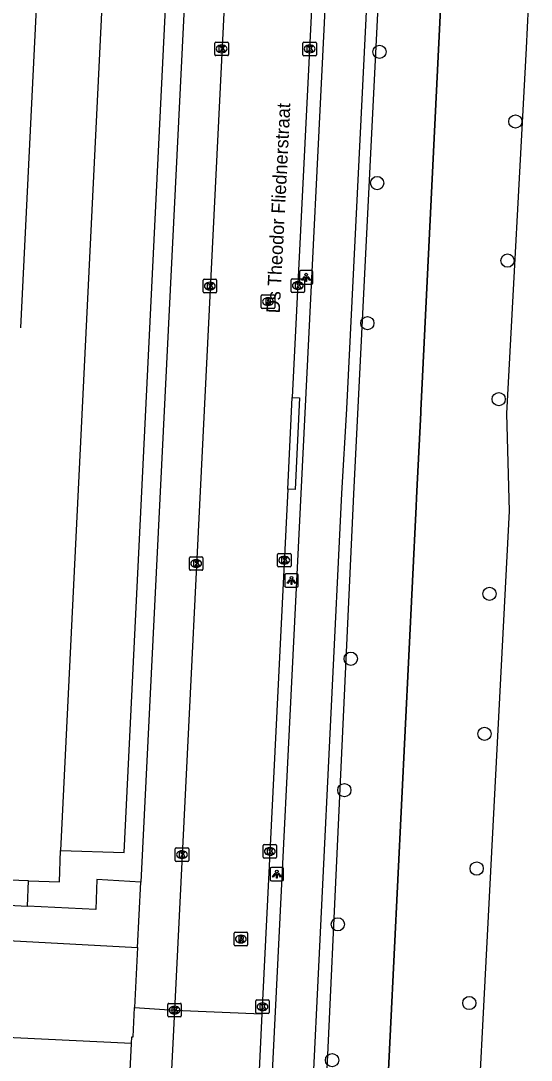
# Model space of a CAD drawing. Extents: x 161761 to 162722, y 384793 to 385405.
# Drawn here: x 162102.1 to 162139.8, y 385048.1 to 385124.9 of the extents above; entities that cross this region are included whole.
import ezdxf

# ---------------------------------------------------------------- set-up
doc = ezdxf.new("R2010")
doc.units = 0
for name, color, linetype in [('IMGEO_Boom', 7, 'Continuous'), ('IMGEO_Fietspad_gesloten', 7, 'Continuous'), ('IMGEO_Groenvoorziening', 7, 'Continuous'), ('IMGEO_Hek', 7, 'Continuous'), ('IMGEO_Kolk', 7, 'Continuous'), ('IMGEO_Lichtpunt', 7, 'Continuous'), ('IMGEO_Openbare_ruimte_label', 7, 'Continuous'), ('IMGEO_Parkeervlak_open', 7, 'Continuous'), ('IMGEO_Rijbaan_lokaal_gesloten', 7, 'Continuous'), ('IMGEO_Rijbaan_lokaal_open', 7, 'Continuous'), ('IMGEO_Rioolput', 7, 'Continuous'), ('IMGEO_Voetpad_open', 7, 'Continuous')]:
    doc.layers.add(name, color=color, linetype=linetype)

msp = doc.modelspace()

# ---------------------------------------------------------------- linework, layer by layer
at = {"layer": 'IMGEO_Boom'}
for centre in [(162128.599, 385122.593), (162138.645, 385117.45), (162128.431, 385112.904), (162138.061, 385107.18), (162127.706, 385102.563), (162137.413, 385096.949), (162136.737, 385082.579), (162126.479, 385077.787), (162136.368, 385072.245), (162126.005, 385068.086), (162135.785, 385062.293), (162125.52, 385058.179), (162135.239, 385052.366), (162125.097, 385048.151)]:
    msp.add_circle(centre, 0.489, dxfattribs=at)
at = {"layer": 'IMGEO_Fietspad_gesloten'}
for points in [[(162134.018, 385254.741), (162126.161, 385096.242), (162125.803, 385089.99), (162122.735, 385027.19)], [(162120.563, 385044.774), (162129.342, 385221.587)]]:
    msp.add_lwpolyline(points, dxfattribs=at)
at = {"layer": 'IMGEO_Groenvoorziening'}
for points in [[(162134.904, 385254.707), (162126.688, 385089.939), (162123.507, 385021.46)], [(162127.975, 385021.202), (162128.056, 385022.862), (162131.31, 385089.036), (162131.34, 385089.671), (162131.648, 385095.933), (162131.658, 385096.124), (162133.367, 385130.823)], [(162139.817, 385130.505), (162139.433, 385122.857), (162137.997, 385095.888), (162138.195, 385088.671), (162134.073, 385009.395)]]:
    msp.add_lwpolyline(points, dxfattribs=at)
at = {"layer": 'IMGEO_Hek'}
for points in [[(162133.367, 385130.823), (162131.658, 385096.124)], [(162131.648, 385095.933), (162131.34, 385089.671)], [(162131.658, 385096.124), (162131.648, 385095.933)], [(162131.31, 385089.036), (162128.056, 385022.862)], [(162131.34, 385089.671), (162131.31, 385089.036)]]:
    msp.add_lwpolyline(points, dxfattribs=at)
at = {"layer": 'IMGEO_Kolk'}
for p, q in [((162116.433, 385122.384), (162116.433, 385123.236)), ((162116.508, 385123.31), (162117.36, 385123.31)), ((162116.921, 385123.09), (162116.946, 385123.09)), ((162117.434, 385123.236), (162117.434, 385122.384)), ((162122.938, 385122.383), (162122.938, 385123.235)), ((162123.013, 385123.309), (162123.865, 385123.309)), ((162123.426, 385123.089), (162123.451, 385123.089)), ((162123.939, 385123.235), (162123.939, 385122.383)), ((162117.36, 385122.31), (162116.508, 385122.31)), ((162116.944, 385122.53), (162116.919, 385122.53)), ((162123.865, 385122.309), (162123.013, 385122.309)), ((162123.449, 385122.529), (162123.424, 385122.529)), ((162122.142, 385105.83), (162122.994, 385105.83)), ((162115.566, 385104.871), (162115.566, 385105.723)), ((162115.641, 385105.797), (162116.493, 385105.797)), ((162116.054, 385105.577), (162116.079, 385105.577)), ((162116.567, 385105.723), (162116.567, 385104.871)), ((162122.067, 385104.904), (162122.067, 385105.756)), ((162122.555, 385105.61), (162122.58, 385105.61)), ((162123.068, 385105.756), (162123.068, 385104.904)), ((162116.493, 385104.797), (162115.641, 385104.797)), ((162116.077, 385105.017), (162116.052, 385105.017)), ((162122.994, 385104.83), (162122.142, 385104.83)), ((162122.578, 385105.05), (162122.553, 385105.05)), ((162114.554, 385084.388), (162114.554, 385085.24)), ((162114.629, 385085.314), (162115.481, 385085.314)), ((162115.555, 385085.24), (162115.555, 385084.388)), ((162121.063, 385084.636), (162121.063, 385085.488)), ((162121.138, 385085.562), (162121.99, 385085.562)), ((162121.551, 385085.342), (162121.576, 385085.342)), ((162122.064, 385085.488), (162122.064, 385084.636)), ((162115.065, 385084.534), (162115.04, 385084.534)), ((162115.042, 385085.094), (162115.067, 385085.094)), ((162121.99, 385084.562), (162121.138, 385084.562)), ((162121.574, 385084.782), (162121.549, 385084.782)), ((162115.481, 385084.314), (162114.629, 385084.314)), ((162113.503, 385062.895), (162113.503, 385063.747)), ((162113.578, 385063.821), (162114.43, 385063.821)), ((162114.504, 385063.747), (162114.504, 385062.895)), ((162119.999, 385063.139), (162119.999, 385063.991)), ((162120.074, 385064.065), (162120.926, 385064.065)), ((162120.487, 385063.845), (162120.512, 385063.845)), ((162121, 385063.991), (162121, 385063.139)), ((162114.014, 385063.041), (162113.989, 385063.041)), ((162113.991, 385063.601), (162114.016, 385063.601)), ((162120.926, 385063.065), (162120.074, 385063.065)), ((162120.51, 385063.285), (162120.485, 385063.285)), ((162114.43, 385062.821), (162113.578, 385062.821)), ((162112.954, 385051.417), (162112.954, 385052.269)), ((162113.029, 385052.343), (162113.881, 385052.343)), ((162113.442, 385052.123), (162113.467, 385052.123)), ((162113.955, 385052.269), (162113.955, 385051.417)), ((162119.453, 385051.668), (162119.453, 385052.52)), ((162119.528, 385052.594), (162120.38, 385052.594)), ((162119.941, 385052.374), (162119.966, 385052.374)), ((162120.454, 385052.52), (162120.454, 385051.668)), ((162113.881, 385051.343), (162113.029, 385051.343)), ((162113.465, 385051.563), (162113.44, 385051.563)), ((162120.38, 385051.594), (162119.528, 385051.594)), ((162119.964, 385051.814), (162119.939, 385051.814))]:
    msp.add_line(p, q, dxfattribs=at)
for points in [[(162116.433, 385122.384), (162116.433, 385123.236)], [(162116.508, 385123.31), (162117.36, 385123.31)], [(162116.754, 385123.01), (162116.877, 385123.01), (162116.877, 385122.859), (162117.007, 385123.01), (162117.171, 385123.01), (162117.025, 385122.859), (162117.178, 385122.61), (162117.026, 385122.61), (162116.941, 385122.774), (162116.877, 385122.707), (162116.877, 385122.61), (162116.754, 385122.61), (162116.754, 385123.01)], [(162117.434, 385123.236), (162117.434, 385122.384)], [(162122.938, 385122.383), (162122.938, 385123.235)], [(162123.013, 385123.309), (162123.865, 385123.309)], [(162123.259, 385123.009), (162123.382, 385123.009), (162123.382, 385122.858), (162123.512, 385123.009), (162123.676, 385123.009), (162123.53, 385122.858), (162123.683, 385122.609), (162123.531, 385122.609), (162123.446, 385122.773), (162123.382, 385122.706), (162123.382, 385122.609), (162123.259, 385122.609), (162123.259, 385123.009)], [(162123.939, 385123.235), (162123.939, 385122.383)], [(162117.36, 385122.31), (162116.508, 385122.31)], [(162123.865, 385122.309), (162123.013, 385122.309)], [(162122.142, 385105.83), (162122.994, 385105.83)], [(162115.566, 385104.871), (162115.566, 385105.723)], [(162115.641, 385105.797), (162116.493, 385105.797)], [(162115.887, 385105.497), (162116.01, 385105.497), (162116.01, 385105.346), (162116.14, 385105.497), (162116.304, 385105.497), (162116.158, 385105.346), (162116.311, 385105.097), (162116.159, 385105.097), (162116.074, 385105.261), (162116.01, 385105.194), (162116.01, 385105.097), (162115.887, 385105.097), (162115.887, 385105.497)], [(162116.567, 385105.723), (162116.567, 385104.871)], [(162122.067, 385104.904), (162122.067, 385105.756)], [(162122.388, 385105.53), (162122.511, 385105.53), (162122.511, 385105.379), (162122.641, 385105.53), (162122.805, 385105.53), (162122.659, 385105.379), (162122.812, 385105.13), (162122.66, 385105.13), (162122.575, 385105.294), (162122.511, 385105.227), (162122.511, 385105.13), (162122.388, 385105.13), (162122.388, 385105.53)], [(162123.068, 385105.756), (162123.068, 385104.904)], [(162116.493, 385104.797), (162115.641, 385104.797)], [(162122.994, 385104.83), (162122.142, 385104.83)], [(162114.554, 385084.388), (162114.554, 385085.24)], [(162114.629, 385085.314), (162115.481, 385085.314)], [(162115.555, 385085.24), (162115.555, 385084.388)], [(162121.063, 385084.636), (162121.063, 385085.488)], [(162121.138, 385085.562), (162121.99, 385085.562)], [(162121.384, 385085.262), (162121.507, 385085.262), (162121.507, 385085.111), (162121.637, 385085.262), (162121.801, 385085.262), (162121.655, 385085.111), (162121.808, 385084.862), (162121.656, 385084.862), (162121.571, 385085.026), (162121.507, 385084.959), (162121.507, 385084.862), (162121.384, 385084.862), (162121.384, 385085.262)], [(162122.064, 385085.488), (162122.064, 385084.636)], [(162114.875, 385085.014), (162114.998, 385085.014), (162114.998, 385084.863), (162115.128, 385085.014), (162115.292, 385085.014), (162115.146, 385084.863), (162115.299, 385084.614), (162115.147, 385084.614), (162115.062, 385084.778), (162114.998, 385084.711), (162114.998, 385084.614), (162114.875, 385084.614), (162114.875, 385085.014)], [(162121.99, 385084.562), (162121.138, 385084.562)], [(162115.481, 385084.314), (162114.629, 385084.314)], [(162113.503, 385062.895), (162113.503, 385063.747)], [(162113.578, 385063.821), (162114.43, 385063.821)], [(162114.504, 385063.747), (162114.504, 385062.895)], [(162119.999, 385063.139), (162119.999, 385063.991)], [(162120.074, 385064.065), (162120.926, 385064.065)], [(162120.32, 385063.765), (162120.443, 385063.765), (162120.443, 385063.614), (162120.573, 385063.765), (162120.737, 385063.765), (162120.591, 385063.614), (162120.744, 385063.365), (162120.592, 385063.365), (162120.507, 385063.529), (162120.443, 385063.462), (162120.443, 385063.365), (162120.32, 385063.365), (162120.32, 385063.765)], [(162121, 385063.991), (162121, 385063.139)], [(162113.824, 385063.521), (162113.947, 385063.521), (162113.947, 385063.37), (162114.077, 385063.521), (162114.241, 385063.521), (162114.095, 385063.37), (162114.248, 385063.121), (162114.096, 385063.121), (162114.011, 385063.285), (162113.947, 385063.218), (162113.947, 385063.121), (162113.824, 385063.121), (162113.824, 385063.521)], [(162120.926, 385063.065), (162120.074, 385063.065)], [(162114.43, 385062.821), (162113.578, 385062.821)], [(162112.954, 385051.417), (162112.954, 385052.269)], [(162113.029, 385052.343), (162113.881, 385052.343)], [(162113.955, 385052.269), (162113.955, 385051.417)], [(162119.453, 385051.668), (162119.453, 385052.52)], [(162119.528, 385052.594), (162120.38, 385052.594)], [(162119.774, 385052.294), (162119.897, 385052.294), (162119.897, 385052.143), (162120.027, 385052.294), (162120.191, 385052.294), (162120.045, 385052.143), (162120.198, 385051.894), (162120.046, 385051.894), (162119.961, 385052.058), (162119.897, 385051.991), (162119.897, 385051.894), (162119.774, 385051.894), (162119.774, 385052.294)], [(162120.454, 385052.52), (162120.454, 385051.668)], [(162113.881, 385051.343), (162113.029, 385051.343)], [(162113.275, 385052.043), (162113.398, 385052.043), (162113.398, 385051.892), (162113.528, 385052.043), (162113.692, 385052.043), (162113.546, 385051.892), (162113.699, 385051.643), (162113.547, 385051.643), (162113.462, 385051.807), (162113.398, 385051.74), (162113.398, 385051.643), (162113.275, 385051.643), (162113.275, 385052.043)], [(162120.38, 385051.594), (162119.528, 385051.594)]]:
    msp.add_lwpolyline(points, dxfattribs=at)
for centre, start, end in [((162116.51, 385123.234), 91.55205, 178.44795), ((162116.51, 385123.234), 91.55205, 178.44795), ((162117.358, 385123.234), 1.55205, 88.44795), ((162117.358, 385123.234), 1.55205, 88.44795), ((162123.015, 385123.233), 91.55205, 178.44795), ((162123.015, 385123.233), 91.55205, 178.44795), ((162123.863, 385123.233), 1.55205, 88.44795), ((162123.863, 385123.233), 1.55205, 88.44795), ((162116.51, 385122.386), 181.55205, 268.44795), ((162116.51, 385122.386), 181.55205, 268.44795), ((162117.358, 385122.386), 271.55205, 358.44795), ((162117.358, 385122.386), 271.55205, 358.44795), ((162123.015, 385122.385), 181.55205, 268.44795), ((162123.015, 385122.385), 181.55205, 268.44795), ((162123.863, 385122.385), 271.55205, 358.44795), ((162123.863, 385122.385), 271.55205, 358.44795), ((162122.144, 385105.754), 91.55205, 178.44795), ((162122.144, 385105.754), 91.55205, 178.44795), ((162122.992, 385105.754), 1.55205, 88.44795), ((162122.992, 385105.754), 1.55205, 88.44795), ((162115.643, 385105.721), 91.55205, 178.44795), ((162115.643, 385105.721), 91.55205, 178.44795), ((162116.491, 385105.721), 1.55205, 88.44795), ((162116.491, 385105.721), 1.55205, 88.44795), ((162115.643, 385104.873), 181.55205, 268.44795), ((162115.643, 385104.873), 181.55205, 268.44795), ((162116.491, 385104.873), 271.55205, 358.44795), ((162116.491, 385104.873), 271.55205, 358.44795), ((162122.144, 385104.906), 181.55205, 268.44795), ((162122.144, 385104.906), 181.55205, 268.44795), ((162122.992, 385104.906), 271.55205, 358.44795), ((162122.992, 385104.906), 271.55205, 358.44795), ((162114.631, 385085.238), 91.55205, 178.44795), ((162114.631, 385085.238), 91.55205, 178.44795), ((162115.479, 385085.238), 1.55205, 88.44795), ((162115.479, 385085.238), 1.55205, 88.44795), ((162121.14, 385085.486), 91.55205, 178.44795), ((162121.14, 385085.486), 91.55205, 178.44795), ((162121.988, 385085.486), 1.55205, 88.44795), ((162121.988, 385085.486), 1.55205, 88.44795), ((162114.631, 385084.39), 181.55205, 268.44795), ((162114.631, 385084.39), 181.55205, 268.44795), ((162115.479, 385084.39), 271.55205, 358.44795), ((162115.479, 385084.39), 271.55205, 358.44795), ((162121.14, 385084.638), 181.55205, 268.44795), ((162121.14, 385084.638), 181.55205, 268.44795), ((162121.988, 385084.638), 271.55205, 358.44795), ((162121.988, 385084.638), 271.55205, 358.44795), ((162113.58, 385063.745), 91.55205, 178.44795), ((162113.58, 385063.745), 91.55205, 178.44795), ((162114.428, 385063.745), 1.55205, 88.44795), ((162114.428, 385063.745), 1.55205, 88.44795), ((162120.076, 385063.989), 91.55205, 178.44795), ((162120.076, 385063.989), 91.55205, 178.44795), ((162120.924, 385063.989), 1.55205, 88.44795), ((162120.924, 385063.989), 1.55205, 88.44795), ((162113.58, 385062.897), 181.55205, 268.44795), ((162113.58, 385062.897), 181.55205, 268.44795), ((162114.428, 385062.897), 271.55205, 358.44795), ((162114.428, 385062.897), 271.55205, 358.44795), ((162120.076, 385063.141), 181.55205, 268.44795), ((162120.076, 385063.141), 181.55205, 268.44795), ((162120.924, 385063.141), 271.55205, 358.44795), ((162120.924, 385063.141), 271.55205, 358.44795), ((162113.031, 385052.267), 91.55205, 178.44795), ((162113.031, 385052.267), 91.55205, 178.44795), ((162113.879, 385052.267), 1.55205, 88.44795), ((162113.879, 385052.267), 1.55205, 88.44795), ((162119.53, 385052.518), 91.55205, 178.44795), ((162119.53, 385052.518), 91.55205, 178.44795), ((162120.378, 385052.518), 1.55205, 88.44795), ((162120.378, 385052.518), 1.55205, 88.44795), ((162113.031, 385051.419), 181.55205, 268.44795), ((162113.031, 385051.419), 181.55205, 268.44795), ((162113.879, 385051.419), 271.55205, 358.44795), ((162113.879, 385051.419), 271.55205, 358.44795), ((162119.53, 385051.67), 181.55205, 268.44795), ((162119.53, 385051.67), 181.55205, 268.44795), ((162120.378, 385051.67), 271.55205, 358.44795), ((162120.378, 385051.67), 271.55205, 358.44795)]:
    msp.add_arc(centre, 0.0765, start, end, dxfattribs=at)
for centre, major_axis, ratio, start_param, end_param in [((162116.92, 385122.81), (-0.387, 0.002), 0.722429, 4.712389, 7.853982), ((162116.945, 385122.81), (-0.39, 0.002), 0.717154, 1.570796, 4.712389), ((162123.425, 385122.809), (-0.387, 0.002), 0.722429, 4.712389, 7.853982), ((162123.45, 385122.809), (-0.39, 0.002), 0.717154, 1.570796, 4.712389), ((162116.053, 385105.297), (-0.387, 0.002), 0.722429, 4.712389, 7.853982), ((162116.078, 385105.297), (-0.39, 0.002), 0.717154, 1.570796, 4.712389), ((162122.554, 385105.33), (-0.387, 0.002), 0.722429, 4.712389, 7.853982), ((162122.579, 385105.33), (-0.39, 0.002), 0.717154, 1.570796, 4.712389), ((162121.55, 385085.062), (-0.387, 0.002), 0.722429, 4.712389, 7.853982), ((162121.575, 385085.062), (-0.39, 0.002), 0.717154, 1.570796, 4.712389), ((162115.041, 385084.814), (-0.387, 0.002), 0.722429, 4.712389, 7.853982), ((162115.066, 385084.814), (-0.39, 0.002), 0.717154, 1.570796, 4.712389), ((162120.486, 385063.565), (-0.387, 0.002), 0.722429, 4.712389, 7.853982), ((162120.511, 385063.565), (-0.39, 0.002), 0.717154, 1.570796, 4.712389), ((162113.99, 385063.321), (-0.387, 0.002), 0.722429, 4.712389, 7.853982), ((162114.015, 385063.321), (-0.39, 0.002), 0.717154, 1.570796, 4.712389), ((162113.441, 385051.843), (-0.387, 0.002), 0.722429, 4.712389, 7.853982), ((162113.466, 385051.843), (-0.39, 0.002), 0.717154, 1.570796, 4.712389), ((162119.94, 385052.094), (-0.387, 0.002), 0.722429, 4.712389, 7.853982), ((162119.965, 385052.094), (-0.39, 0.002), 0.717154, 1.570796, 4.712389)]:
    msp.add_ellipse(centre, major_axis=major_axis, ratio=ratio, start_param=start_param, end_param=end_param, dxfattribs=at)
at = {"layer": 'IMGEO_Lichtpunt'}
for p, q in [((162122.682, 385106.343), (162122.682, 385105.536)), ((162122.682, 385106.343), (162122.682, 385105.536)), ((162123.584, 385106.438), (162122.776, 385106.438)), ((162123.584, 385106.438), (162122.776, 385106.438)), ((162123.678, 385105.536), (162123.678, 385106.343)), ((162123.678, 385105.536), (162123.678, 385106.343)), ((162122.776, 385105.442), (162123.584, 385105.442)), ((162122.776, 385105.442), (162123.584, 385105.442)), ((162121.595, 385083.966), (162121.595, 385083.159)), ((162121.595, 385083.966), (162121.595, 385083.159)), ((162122.497, 385084.061), (162121.689, 385084.061)), ((162122.497, 385084.061), (162121.689, 385084.061)), ((162122.591, 385083.159), (162122.591, 385083.966)), ((162122.591, 385083.159), (162122.591, 385083.966)), ((162121.689, 385083.065), (162122.497, 385083.065)), ((162121.689, 385083.065), (162122.497, 385083.065)), ((162120.519, 385062.285), (162120.519, 385061.478)), ((162120.519, 385062.285), (162120.519, 385061.478)), ((162121.421, 385062.38), (162120.613, 385062.38)), ((162121.421, 385062.38), (162120.613, 385062.38)), ((162121.515, 385061.478), (162121.515, 385062.285)), ((162121.515, 385061.478), (162121.515, 385062.285)), ((162120.613, 385061.384), (162121.421, 385061.384)), ((162120.613, 385061.384), (162121.421, 385061.384))]:
    msp.add_line(p, q, dxfattribs=at)
for points in [[(162123.056, 385106.007), (162123.095, 385105.979), (162122.907, 385105.717), (162122.869, 385105.744), (162123.056, 385106.007)], [(162123.158, 385105.959), (162123.205, 385105.959), (162123.205, 385105.637), (162123.158, 385105.637), (162123.158, 385105.959)], [(162123.268, 385105.979), (162123.306, 385106.006), (162123.493, 385105.744), (162123.454, 385105.716), (162123.268, 385105.979)], [(162121.969, 385083.63), (162122.008, 385083.602), (162121.82, 385083.34), (162121.782, 385083.367), (162121.969, 385083.63)], [(162122.071, 385083.582), (162122.118, 385083.582), (162122.118, 385083.26), (162122.071, 385083.26), (162122.071, 385083.582)], [(162122.181, 385083.602), (162122.219, 385083.629), (162122.406, 385083.367), (162122.367, 385083.339), (162122.181, 385083.602)], [(162120.893, 385061.949), (162120.932, 385061.921), (162120.744, 385061.659), (162120.706, 385061.686), (162120.893, 385061.949)], [(162120.995, 385061.901), (162121.042, 385061.901), (162121.042, 385061.579), (162120.995, 385061.579), (162120.995, 385061.901)], [(162121.105, 385061.921), (162121.143, 385061.948), (162121.33, 385061.686), (162121.291, 385061.658), (162121.105, 385061.921)]]:
    msp.add_lwpolyline(points, dxfattribs=at)
for centre in [(162123.181, 385106.141), (162122.094, 385083.764), (162121.018, 385062.083)]:
    msp.add_circle(centre, 0.0994, dxfattribs=at)
for centre, start, end in [((162122.776, 385106.343), 90, 180), ((162122.776, 385106.343), 90, 180), ((162123.584, 385106.343), 0, 90), ((162123.584, 385106.343), 0, 90), ((162122.776, 385105.536), 180, 270), ((162122.776, 385105.536), 180, 270), ((162123.584, 385105.536), 270, 0), ((162123.584, 385105.536), 270, 360), ((162121.689, 385083.966), 90, 180), ((162121.689, 385083.966), 90, 180), ((162122.497, 385083.966), 0, 90), ((162122.497, 385083.966), 0, 90), ((162121.689, 385083.159), 180, 270), ((162121.689, 385083.159), 180, 270), ((162122.497, 385083.159), 270, 0), ((162122.497, 385083.159), 270, 360), ((162120.613, 385062.285), 90, 180), ((162120.613, 385062.285), 90, 180), ((162121.421, 385062.285), 0, 90), ((162121.421, 385062.285), 0, 90), ((162120.613, 385061.478), 180, 270), ((162120.613, 385061.478), 180, 270), ((162121.421, 385061.478), 270, 0), ((162121.421, 385061.478), 270, 360)]:
    msp.add_arc(centre, 0.0946, start, end, dxfattribs=at)
at = {"layer": 'IMGEO_Parkeervlak_open'}
msp.add_lwpolyline([(162105.027, 385063.631), (162109.738, 385063.476), (162117.379, 385219.314), (162112.671, 385219.545)], dxfattribs=at)
at = {"layer": 'IMGEO_Rijbaan_lokaal_gesloten'}
for points in [[(162128.368, 385221.63), (162122.159, 385097.081)], [(162121.802, 385220.491), (162113.455, 385051.843)], [(162121.833, 385090.293), (162122.159, 385097.081)], [(162121.833, 385090.293), (162119.917, 385051.572)], [(162113.455, 385051.843), (162112.559, 385034.271)], [(162113.455, 385051.843), (162119.917, 385051.572)], [(162119.917, 385051.572), (162119.581, 385044.789)]]:
    msp.add_lwpolyline(points, dxfattribs=at)
at = {"layer": 'IMGEO_Rijbaan_lokaal_open'}
for points in [[(162112.671, 385219.545), (162105.027, 385063.631)], [(162102.091, 385102.227), (162106.5, 385192.162)], [(162102.662, 385061.388), (162104.951, 385061.313), (162105.027, 385063.631)], [(162102.662, 385061.388), (162101.235, 385061.435)]]:
    msp.add_lwpolyline(points, dxfattribs=at)
at = {"layer": 'IMGEO_Rioolput'}
for p, q in [((162119.863, 385103.723), (162119.863, 385104.575)), ((162119.938, 385104.649), (162120.79, 385104.649)), ((162120.351, 385104.429), (162120.376, 385104.429)), ((162120.864, 385104.575), (162120.864, 385103.723)), ((162120.79, 385103.649), (162119.938, 385103.649)), ((162120.374, 385103.869), (162120.349, 385103.869)), ((162117.858, 385056.666), (162117.858, 385057.518)), ((162117.933, 385057.592), (162118.785, 385057.592)), ((162118.859, 385057.518), (162118.859, 385056.666)), ((162118.369, 385056.812), (162118.344, 385056.812)), ((162118.346, 385057.372), (162118.371, 385057.372)), ((162118.785, 385056.592), (162117.933, 385056.592))]:
    msp.add_line(p, q, dxfattribs=at)
for points in [[(162119.863, 385103.723), (162119.863, 385104.575)], [(162119.938, 385104.649), (162120.79, 385104.649)], [(162120.452, 385104.347), (162120.2, 385104.349), (162120.2, 385103.949)], [(162120.864, 385104.575), (162120.864, 385103.723)], [(162120.79, 385103.649), (162119.938, 385103.649)], [(162120.2, 385103.949), (162120.324, 385103.949), (162120.324, 385104.111), (162120.335, 385104.111)], [(162120.378, 385104.268), (162120.324, 385104.268), (162120.324, 385104.187)], [(162120.324, 385104.187), (162120.376, 385104.187)], [(162120.382, 385104.082), (162120.453, 385103.949), (162120.593, 385103.949), (162120.528, 385104.075)], [(162117.858, 385056.666), (162117.858, 385057.518)], [(162117.933, 385057.592), (162118.785, 385057.592)], [(162118.859, 385057.518), (162118.859, 385056.666)], [(162118.447, 385057.29), (162118.195, 385057.292), (162118.195, 385056.892)], [(162118.195, 385056.892), (162118.319, 385056.892), (162118.319, 385057.054), (162118.33, 385057.054)], [(162118.373, 385057.211), (162118.319, 385057.211), (162118.319, 385057.13)], [(162118.319, 385057.13), (162118.371, 385057.13)], [(162118.377, 385057.025), (162118.448, 385056.892), (162118.588, 385056.892), (162118.523, 385057.018)], [(162118.785, 385056.592), (162117.933, 385056.592)]]:
    msp.add_lwpolyline(points, dxfattribs=at)
for centre, radius, start, end in [((162119.94, 385104.573), 0.0765, 91.55205, 178.44795), ((162119.94, 385104.573), 0.0765, 91.55205, 178.44795), ((162120.451, 385104.237), 0.109, 350.36119, 89.41601), ((162120.788, 385104.573), 0.0765, 1.55205, 88.44795), ((162120.788, 385104.573), 0.0765, 1.55205, 88.44795), ((162119.94, 385103.725), 0.0765, 181.55205, 268.44795), ((162119.94, 385103.725), 0.0765, 181.55205, 268.44795), ((162120.334, 385104.058), 0.0533, 26.02933, 88.69889), ((162120.36, 385104.376), 0.19, 274.7715, 282.96867), ((162120.384, 385104.172), 0.0964, 77.00612, 93.18647), ((162120.398, 385104.229), 0.0378, 276.66336, 79.67722), ((162120.449, 385104.237), 0.112, 277.58423, 350.98172), ((162120.433, 385104.022), 0.108, 29.51342, 73.79051), ((162120.788, 385103.725), 0.0765, 271.55205, 358.44795), ((162120.788, 385103.725), 0.0765, 271.55205, 358.44795), ((162117.935, 385057.516), 0.0765, 91.55205, 178.44795), ((162117.935, 385057.516), 0.0765, 91.55205, 178.44795), ((162118.783, 385057.516), 0.0765, 1.55205, 88.44795), ((162118.783, 385057.516), 0.0765, 1.55205, 88.44795), ((162118.329, 385057.001), 0.0533, 26.02933, 88.69889), ((162118.355, 385057.319), 0.19, 274.7715, 282.96867), ((162118.379, 385057.115), 0.0964, 77.00612, 93.18647), ((162118.393, 385057.172), 0.0378, 276.66336, 79.67722), ((162118.446, 385057.18), 0.109, 350.36119, 89.41601), ((162118.444, 385057.18), 0.112, 277.58423, 350.98172), ((162118.428, 385056.965), 0.108, 29.51342, 73.79051), ((162117.935, 385056.668), 0.0765, 181.55205, 268.44795), ((162117.935, 385056.668), 0.0765, 181.55205, 268.44795), ((162118.783, 385056.668), 0.0765, 271.55205, 358.44795), ((162118.783, 385056.668), 0.0765, 271.55205, 358.44795)]:
    msp.add_arc(centre, radius, start, end, dxfattribs=at)
for centre, major_axis, ratio, start_param, end_param in [((162120.35, 385104.149), (-0.387, 0.002), 0.722429, 4.712389, 7.853982), ((162120.375, 385104.149), (-0.39, 0.002), 0.717154, 1.570796, 4.712389), ((162118.345, 385057.092), (-0.387, 0.002), 0.722429, 4.712389, 7.853982), ((162118.37, 385057.092), (-0.39, 0.002), 0.717154, 1.570796, 4.712389)]:
    msp.add_ellipse(centre, major_axis=major_axis, ratio=ratio, start_param=start_param, end_param=end_param, dxfattribs=at)
at = {"layer": 'IMGEO_Voetpad_open'}
for points in [[(162117.695, 385196.978), (162110.957, 385061.285)], [(162122.159, 385097.081), (162122.689, 385097.04), (162122.36, 385090.281), (162121.833, 385090.293)], [(162110.957, 385061.285), (162107.717, 385061.481), (162107.644, 385059.262), (162102.6, 385059.511)], [(162102.6, 385059.511), (162102.662, 385061.388)], [(162110.718, 385056.47), (162110.957, 385061.285)], [(162101.174, 385059.581), (162102.6, 385059.511)], [(162080.425, 385054.04), (162100.934, 385052.997), (162101.165, 385056.984), (162110.718, 385056.47)], [(162110.718, 385056.47), (162110.497, 385052.03)], [(162110.275, 385049.383), (162110.3, 385049.877), (162110.397, 385049.875), (162110.497, 385052.03)], [(162110.497, 385052.03), (162113.455, 385051.843)], [(162110.275, 385049.383), (162085.205, 385050.596)], [(162109.696, 385037.936), (162110.275, 385049.383)]]:
    msp.add_lwpolyline(points, dxfattribs=at)

# ---------------------------------------------------------------- texts
at = {"layer": 'IMGEO_Openbare_ruimte_label'}
msp.add_text('Ds Theodor Fliednerstraat', height=1, rotation=87.07753, dxfattribs=at).set_placement((162121.229, 385103.271))

doc.saveas('drawing.dxf')
